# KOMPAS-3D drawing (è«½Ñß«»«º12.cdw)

Referenced files: КолесоМой01.cdw
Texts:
  Колесо зубчатое
  OlegKR
  Noncommercial version
  Ra1.25
  Ra3.2
  Ra1.6
  Модуль нормальный
  Число зубьев
  Угол наклона зубьев
  Направление линии зуба
  Исходный контур
  Коэффициент смещения
  исходного контура
  Степень точности
  по ГОСТ 1643-81
  Делительный диаметр
  Symbol type A
  Левое
  ГОСТ 13755-81
  Ra12.5
  Термообработка, улучшение 210 НВ.
  Радиусы скруглений 1,6 max.
  Неуказанные предельные размеры отверстий +t 2 , валов -t 2 , остальных  t 2 /2, по ГОСТ 30893.1-2002.
  Сталь 45   ГОСТ 1050-88
Dimensions and other numbers on the sheet: 1; 2 фаски; 20; 50; 4 отв.; 26; 2 фаски 1; 1,6; 68; 120; 170; 193,52; 0.025; 0.012; 14; 52,6; 45; 2; 94; 5; 0,0; 8-С; 189,52; 1:1; 1,5; 0; 3; 4; 6; 7; 8; 9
